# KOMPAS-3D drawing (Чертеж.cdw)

Views: Спереди 1, Проекционный вид 2, Проекционный вид 3, Разрез А-А, Спереди 5
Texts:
  Vika
Dimensions and other numbers on the sheet: 62; 8; 18; 70; 90; 47,3; 41; 40; 48; 60; 30; 1:1; 1; 0; 2; 3; 4; 5; 6; 7; 9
